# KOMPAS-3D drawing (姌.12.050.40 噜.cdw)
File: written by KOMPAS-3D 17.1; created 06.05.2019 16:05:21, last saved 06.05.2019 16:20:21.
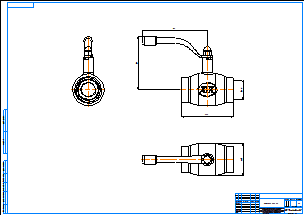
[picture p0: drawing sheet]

Sheet 1: A1, landscape

Title block, sheet 1: name: КШ.12.050.40 рр; material: Внимание! Данный продукт является объектом авторского права ООО «Торговый Дом АДЛ». / Запрещается изменение, копирование, распространение / (в том числе путем копирования на другие сайты и ресурсы в Интернете) / или любое иное использование информации и объектов без предварительного / согласия правообладателя (ООО «Торговый Дом АДЛ»).; scale: 1:1; sheets: 1; organisation: ООО "Торговый дом АДЛ"; sheet format: A1; stored path: C:\Users\tra\Desktop\2д чертежи\Шаровые краны БИВАЛ\КШ_Бивал_серия_11_12\KOMPAS_2D\КШ.12.050.40 рр.cdw

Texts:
  user
  RG 2"
Dimensions and other numbers on the sheet: 145; 148; 180; 88,9; 1:1; 1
